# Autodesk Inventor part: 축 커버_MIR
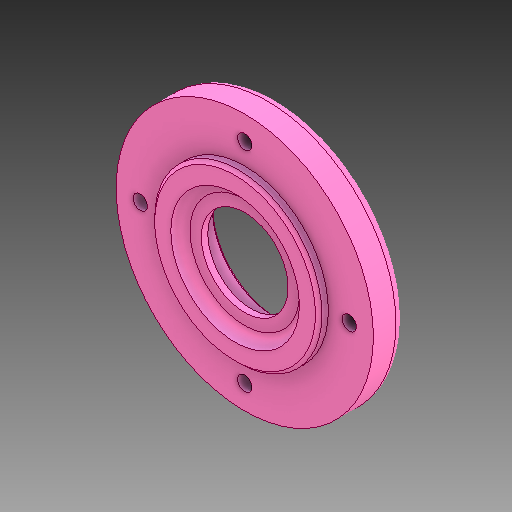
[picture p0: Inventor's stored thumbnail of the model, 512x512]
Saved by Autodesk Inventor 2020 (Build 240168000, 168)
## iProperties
Created: 2015-10
Part Number: 축 커버_MIR
Material: 강철, 연강
Document SubType Name: Modeling
Designer: Administrator
Density: 7.86 g/cm^3
Appearance: 강철
Author: mdu
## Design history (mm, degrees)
derived "축 커버.ipt"
  sketch "스케치1"
    geometry: C1 r 40 at (0, 0) reference; C2 r 26 at (0, 0) reference; 1 further point
    dimensions: "d0" = 10 dimension on point (0, 0) C1.centre C1 C2.centre C2
  sketch "스케치2"
    geometry: C1 r 20 at (0, 0) reference; 1 further point
    dimensions: "d0" = 10 dimension on point (0, 0) C1.centre C1
  sketch "스케치3"
    geometry: C1 r 1.621 at (0, 32.5) reference; 1 further point
    dimensions: "d0" = 10 dimension on point (0, 0) C1.centre C1
feature "솔리드1::축 커버.ipt"
tag "피쳐 태그1"
node "솔리드1"
